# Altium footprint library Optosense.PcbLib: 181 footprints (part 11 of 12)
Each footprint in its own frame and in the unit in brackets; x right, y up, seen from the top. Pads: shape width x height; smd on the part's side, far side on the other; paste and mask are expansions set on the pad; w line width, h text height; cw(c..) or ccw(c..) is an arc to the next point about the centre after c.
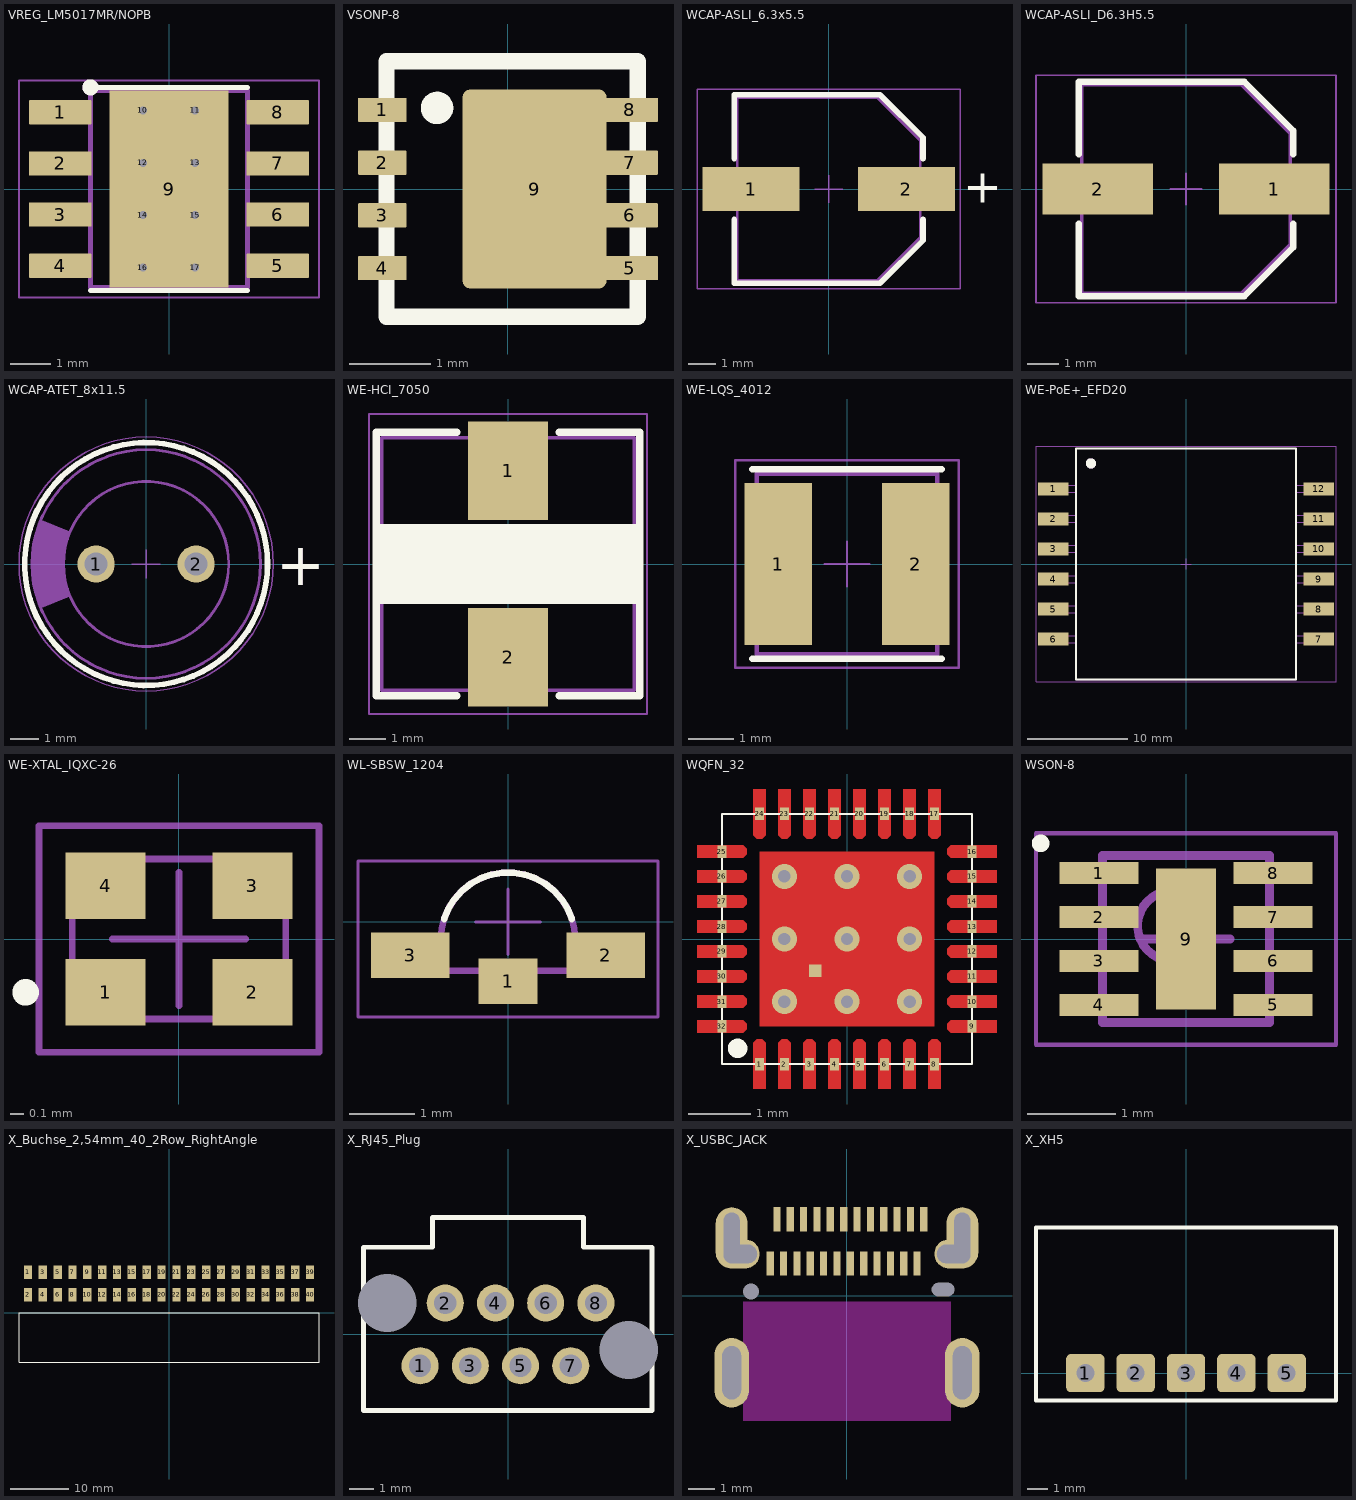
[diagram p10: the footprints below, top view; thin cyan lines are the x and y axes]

## VREG_LM5017MR/NOPB [mm]
pads (17):
  rrect5% 1.55x0.6 smd mask+0: 1(-2.7,1.905) 2(-2.7,0.635) 3(-2.7,-0.635) 4(-2.7,-1.905) 5(2.7,-1.905) 6(2.7,-0.635) 7(2.7,0.635) 8(2.7,1.905)
  rect 2.95x4.9 smd paste-3 mask+0: 9(0,0)
  round 0.3 hole 0.2: 10(-0.65,1.95) 11(0.65,1.95) 12(-0.65,0.65) 13(0.65,0.65) 14(-0.65,-0.65) 15(0.65,-0.65) 16(-0.65,-1.95) 17(0.65,-1.95)
Top Overlay:
  circle w0.2: c-1.95,2.525 r0.1
  lines w0.127: -1.95,-2.525 1.95,-2.525 ; -1.95,2.525 1.95,2.525
Top Paste:
  region: 1.355,-1.7 -1.355,-1.7 -1.355,1.7 1.355,1.7
Top Solder:
  drawing of 9 lines, arcs and shapes, not listed
Mechanical 13:
  circle w0.2: c-1.95,2.525 r0.1
  lines w0.127: -1.95,-2.45 -1.95,2.45 1.95,2.45 1.95,-2.45 -1.95,-2.45
Mechanical 15:
  lines w0.05: -3.725,-2.7 -3.725,2.7 3.725,2.7 3.725,-2.7 -3.725,-2.7
3D body "DRV8871DDA.STEP": height 1.7, standoff 0, extent -3,-2.45 3,2.45

## VSONP-8 [mm] "CSD25402Q3A"
pads (9):
  rrect10% 0.6x0.3 smd mask+0.05: 1(-1.55,0.975) 2(-1.55,0.325) 3(-1.55,-0.325) 4(-1.55,-0.975)
  rrect10% 0.7x0.3 smd mask+0.05: 5(1.5,-0.975) 6(1.5,-0.325) 7(1.5,0.325) 8(1.5,0.975)
  rrect10% 1.775x2.45 smd paste-0.55 mask+0.05: 9(0.327,0)
Top Overlay:
  circle w0.2: c-0.875,1 r0.1
  lines w0.2: -1.5,-1.575 1.6,-1.575 1.6,1.575 -1.5,1.575 -1.5,-1.575
3D body "User Library-8-VSONP3x3.step": height 0.9, standoff 0, extent -1.986,-1.9 1.784,1.9

## WCAP-ASLI_6.3x5.5 [mm] "Aluminium Electrolytic V-Chip SMT Capacitors, 6.3x5.5mm"
height 5.5
pads (2):
  rect 3.5x1.6 smd: 1(-2.8,0) 2(2.8,0)
Top Overlay:
  lines w0.2: -3.4,-1.1 -3.4,-3.4 1.85,-3.4 3.4,-1.85 3.4,-1.1 ; -3.4,1.1 -3.4,3.4 1.85,3.4 3.4,1.85 3.4,1.1
  text "+" at 4.85,-0.5 h1.22
Mechanical 13:
  lines w0.1: -3.3,-3.3 1.75,-3.3 3.3,-1.75 3.3,1.75 1.75,3.3 -3.3,3.3 -3.3,-3.3
Mechanical 15:
  lines w0.05: -0.5,0 0.5,0 ; 0,-0.5 0,0.5 ; -4.75,-3.6 -4.75,3.6 4.75,3.6 4.75,-3.6 -4.75,-3.6
3D body "6.3x5.5x2.2.stp": height 5.5, standoff 0, extent -3.65,-3.3 3.65,3.3

## WCAP-ASLI_D6.3H5.5 [mm] "Aluminium Electrolytic V-Chip SMT Capacitors, 6.3x5.5mm"
height 5.5
pads (2):
  rect 3.5x1.6 smd: 1(2.8,0) 2(-2.8,0)
Top Overlay:
  lines w0.2: -3.4,-1.1 -3.4,-3.4 1.85,-3.4 3.4,-1.85 3.4,-1.1 ; -3.4,1.1 -3.4,3.4 1.85,3.4 3.4,1.85 3.4,1.1
Mechanical 11:
  lines w0.1: -3.3,-3.3 -3.3,3.3 1.75,3.3 3.3,1.75 3.3,-1.75 1.75,-3.3 -3.3,-3.3
  text ".Designator" at -2.5,-0.75 h1.5
Mechanical 15:
  lines w0.05: -0.5,0 0.5,0 ; 0,-0.5 0,0.5 ; -4.75,-3.6 4.75,-3.6 4.75,3.6 -4.75,3.6 -4.75,-3.6
3D body "6.3x5.5x2.2.stp": height 5.5, standoff 0, extent -3.65,-3.3 3.65,3.3

## WCAP-ATET_8x11.5 [mm] "Aluminum Electrolytic Capacitors, 8x11.5mm"
height 13
pads (2):
  round 1.3 hole 0.8: 1(-1.75,0) 2(1.75,0)
Top Overlay:
  circle w0.2: c0,0 r4.25
  text "+" at 4.55,-0.75 h1.5
Mechanical 13:
  circle w0.1: c0,0 r2.89
  circle w0.1: c0,0 r4
  region: -3.685,-1.557 -3.762,-1.372 -3.881,-0.99 -3.96,-0.598 -4,-0.2 -4,0.2 -3.96,0.598 -3.881,0.99 -3.762,1.372 -3.685,1.557 -2.662,1.125 -2.662,1.124 -2.715,0.99 -2.8,0.714 -2.858,0.431 -2.886,0.144 -2.886,-0.144 -2.858,-0.431 -2.8,-0.714 -2.715,-0.99 -2.662,-1.124 -2.662,-1.125
Mechanical 15:
  circle w0.05: c0,0 r4.45
  lines w0.05: -0.5,0 0.5,0 ; 0,-0.5 0,0.5
3D body "8x11.5x3.5x0.5.stp": height 11.76, standoff -19.96, extent -3.99,-4 4,3.999

## WE-HCI_7050 [mm] "SMT Flat Wire High Current Inductor, body 6.9x6.9mm"
height 4.8
pads (2):
  rect 2.2x2.7 smd: 1(0,2.55) 2(0,-2.55)
Top Overlay:
  rectangle: -3.6,-1.092 3.6,1.092
  lines w0.2: -1.4,-3.6 -3.6,-3.6 -3.6,3.6 -1.4,3.6 ; 1.4,-3.6 3.6,-3.6 3.6,3.6 1.4,3.6
Mechanical 13:
  lines w0.1: -3.45,-3.45 -3.45,3.45 3.45,3.45 3.45,-3.45 -3.45,-3.45
Mechanical 15:
  lines w0.05: -0.5,0 0.5,0 ; 0,-0.5 0,0.5 ; -3.8,-4.1 -3.8,4.1 3.8,4.1 3.8,-4.1 -3.8,-4.1
3D body "744314xxx.stp": height 5, standoff 0, extent -3.45,-3.5 3.45,3.5

## WE-LQS_4012 [mm] "SMD Power Inductor, 2-Leads, body 4x4mm"
height 1.2
pads (2):
  rect 1.5x3.6 smd: 1(-1.525,0) 2(1.525,0)
Top Overlay:
  lines w0.15: -2.1,-2.1 2.1,-2.1 ; -2.1,2.1 2.1,2.1
Top 3D Body:
  lines w0.1: -2,-2 2,-2 2,2 -2,2 -2,-2
Top Courtyard:
  lines w0.05: -0.5,0 0.5,0 ; 0,-0.5 0,0.5 ; -2.475,-2.3 -2.475,2.3 2.475,2.3 2.475,-2.3 -2.475,-2.3
Top Component Outline:
  lines w0.1: -2,-2 2,-2 2,2 -2,2 -2,-2
Top Designator:
  text ".Designator" at -4.998,-0.333 h1
3D body "IndLQS_4012.stp": height 1.19, standoff -0.01, extent -2,-2 2,2

## WE-PoE+_EFD20 [mm] "Power over Ethernet Plus Transformer, size EFD20"
height 11.43
pads (12):
  rect 3.05x1.27 smd: 1(-13.26,7.5) 2(-13.26,4.5) 3(-13.26,1.5) 4(-13.26,-1.5) 5(-13.26,-4.5) 6(-13.26,-7.5) 7(13.26,-7.5) 8(13.26,-4.5) 9(13.26,-1.5) 10(13.26,1.5) 11(13.26,4.5) 12(13.26,7.5)
Top Overlay:
  circle w0.8: c-9.5,10.055 r0.1
  lines w0.2: -11,-11.555 -11,11.555 11,11.555 11,-11.555 -11,-11.555
Mechanical 13:
  circle w0.8: c-9.5,10.055 r0.1
  lines w0.1: -11,-7.85 -14.54,-7.85 -14.54,-7.15 -11,-7.15 ; -11,-4.85 -14.54,-4.85 -14.54,-4.15 -11,-4.15 ; -11,-1.85 -14.54,-1.85 -14.54,-1.15 -11,-1.15 ; -11,1.15 -14.54,1.15 -14.54,1.85 -11,1.85 ; -11,4.15 -14.54,4.15 -14.54,4.85 -11,4.85 ; -11,7.15 -14.54,7.15 -14.54,7.85 -11,7.85 ; 11,-7.85 14.54,-7.85 14.54,-7.15 11,-7.15 ; 11,-4.85 14.54,-4.85 14.54,-4.15 11,-4.15 ; 11,-1.85 14.54,-1.85 14.54,-1.15 11,-1.15 ; 11,1.15 14.54,1.15 14.54,1.85 11,1.85 ; 11,4.15 14.54,4.15 14.54,4.85 11,4.85 ; 11,7.15 14.54,7.15 14.54,7.85 11,7.85 ; -11,-11.555 -11,11.555 11,11.555 11,-11.555 -11,-11.555
Mechanical 15:
  lines w0.05: -0.5,0 0.5,0 ; 0,-0.5 0,0.5 ; -14.985,-11.755 -14.985,11.755 14.985,11.755 14.985,-11.755 -14.985,-11.755
3D body "EFD20_7491194501.stp": height 11.43, standoff 0, extent -14.54,-10 14.54,10

## WE-XTAL_IQXC-26 [mm] "Quartz Crystal, size IQXC-26, body 1.6x1.2mm"
height 0.4
pads (4):
  rect 0.6x0.5 smd: 1(-0.55,-0.4) 2(0.55,-0.4) 3(0.55,0.4) 4(-0.55,0.4)
Top Overlay:
  circle w0.1: c-1.15,-0.4 r0.05
Mechanical 11:
  circle w0.05: c-0.6,-0.4 r0.1
  lines w0.05: -0.8,-0.6 0.8,-0.6 0.8,0.6 -0.8,0.6 -0.8,-0.6
  text ".Designator" at -0.6,-0.25 h0.5
Mechanical 13:
  lines w0.05: -0.8,-0.6 -0.8,0.6 0.8,0.6 0.8,-0.6 -0.8,-0.6
Mechanical 15:
  lines w0.05: -0.5,0 0.5,0 ; 0,-0.5 0,0.5 ; -1.05,-0.85 -1.05,0.85 1.05,0.85 1.05,-0.85 -1.05,-0.85
3D body "FrqXTAL_IQXC-26.stp": height 0.4, standoff 0, extent -0.8,-0.6 0.8,0.6

## WL-SBSW_1204 [mm] "SMD Bi-color Side view Waterclear, body 3.2x1mm"
height 1
pads (3):
  rect 0.9x0.7 smd: 1(0,-0.91)
  rect 1.2x0.7 smd: 2(1.5,-0.51) 3(-1.5,-0.51)
Top Overlay:
  lines w0.1: -0.979,0.043 cw(c0,-0.27) 0.979,0.043
Mechanical 13:
  lines w0.1: -1.6,-0.75 1.6,-0.75 1.6,-0.27 1.028,-0.27 ccw(c0,-0.27) -1.028,-0.27 -1.6,-0.27 -1.6,-0.75
Mechanical 15:
  lines w0.05: -0.5,0 0.5,0 ; 0,-0.5 0,0.5 ; -2.3,-1.46 2.3,-1.46 2.3,0.935 -2.3,0.935 -2.3,-1.46
3D body "155124xx73200.stp": height 1.02, standoff 0.02, extent -1.6,-0.765 1.6,0.735

## WQFN_32 [mm]
pads (33):
  rect 0.15x0.2 smd paste+0 mask+0: 1(-1.4,-2) 2(-1,-2) 3(-0.6,-2) 4(-0.2,-2) 5(0.2,-2) 6(0.6,-2) 7(1,-2) 8(1.4,-2) 9(2,-1.4) 10(2,-1) 11(2,-0.6) 12(2,-0.2) 13(2,0.2) 14(2,0.6) 15(2,1) 16(2,1.4) 17(1.4,2) 18(1,2) 19(0.6,2) 20(0.2,2) 21(-0.2,2) 22(-0.6,2) 23(-1,2) 24(-1.4,2) 25(-2,1.4) 26(-2,1) 27(-2,0.6) 28(-2,0.2) 29(-2,-0.2) 30(-2,-0.6) 31(-2,-1) 32(-2,-1.4)
  rect 0.2x0.2 smd paste+0 mask+0: Pad(-0.508,-0.508)
via 1,0 diameter 0.4 hole 0.2
via 0,0 diameter 0.4 hole 0.2
via -1,0 diameter 0.4 hole 0.2
via -1,-1 diameter 0.4 hole 0.2
via 1,-1 diameter 0.4 hole 0.2
via 0,-1 diameter 0.4 hole 0.2
via -1,1 diameter 0.4 hole 0.2
via 1,1 diameter 0.4 hole 0.2
via 0,1 diameter 0.4 hole 0.2
Top Layer:
  rectangle: -1.4,-1.4 1.4,1.4
  region: -2.4,1.5 -2.4,1.3 -1.7,1.3 -1.659,1.3 -1.6,1.359 -1.6,1.441 -1.659,1.5 -1.7,1.5
  region: -2.4,1.1 -2.4,0.9 -1.7,0.9 -1.659,0.9 -1.6,0.959 -1.6,1.041 -1.659,1.1 -1.7,1.1
  region: -2.4,0.7 -2.4,0.5 -1.7,0.5 -1.659,0.5 -1.6,0.559 -1.6,0.641 -1.659,0.7 -1.7,0.7
  region: -2.4,0.3 -2.4,0.1 -1.7,0.1 -1.659,0.1 -1.6,0.159 -1.6,0.241 -1.659,0.3 -1.7,0.3
  region: -2.4,-0.1 -2.4,-0.3 -1.7,-0.3 -1.659,-0.3 -1.6,-0.241 -1.6,-0.159 -1.659,-0.1 -1.7,-0.1
  region: -2.4,-0.5 -2.4,-0.7 -1.7,-0.7 -1.659,-0.7 -1.6,-0.641 -1.6,-0.559 -1.659,-0.5 -1.7,-0.5
  region: -2.4,-0.9 -2.4,-1.1 -1.7,-1.1 -1.659,-1.1 -1.6,-1.041 -1.6,-0.959 -1.659,-0.9 -1.7,-0.9
  region: -1.3,2.4 -1.5,2.4 -1.5,1.7 -1.5,1.659 -1.441,1.6 -1.359,1.6 -1.3,1.659 -1.3,1.7
  region: -0.9,2.4 -1.1,2.4 -1.1,1.7 -1.1,1.659 -1.041,1.6 -0.959,1.6 -0.9,1.659 -0.9,1.7
  region: -0.5,2.4 -0.7,2.4 -0.7,1.7 -0.7,1.659 -0.641,1.6 -0.559,1.6 -0.5,1.659 -0.5,1.7
  region: -0.1,2.4 -0.3,2.4 -0.3,1.7 -0.3,1.659 -0.241,1.6 -0.159,1.6 -0.1,1.659 -0.1,1.7
  region: 0.3,2.4 0.1,2.4 0.1,1.7 0.1,1.659 0.159,1.6 0.241,1.6 0.3,1.659 0.3,1.7
  region: 0.7,2.4 0.5,2.4 0.5,1.7 0.5,1.659 0.559,1.6 0.641,1.6 0.7,1.659 0.7,1.7
  region: 1.1,2.4 0.9,2.4 0.9,1.7 0.9,1.659 0.959,1.6 1.041,1.6 1.1,1.659 1.1,1.7
  region: 2.4,-1.5 2.4,-1.3 1.7,-1.3 1.659,-1.3 1.6,-1.359 1.6,-1.441 1.659,-1.5 1.7,-1.5
  region: 2.4,1.3 2.4,1.5 1.7,1.5 1.659,1.5 1.6,1.441 1.6,1.359 1.659,1.3 1.7,1.3
  region: 2.4,0.9 2.4,1.1 1.7,1.1 1.659,1.1 1.6,1.041 1.6,0.959 1.659,0.9 1.7,0.9
  region: 2.4,0.5 2.4,0.7 1.7,0.7 1.659,0.7 1.6,0.641 1.6,0.559 1.659,0.5 1.7,0.5
  region: 2.4,0.1 2.4,0.3 1.7,0.3 1.659,0.3 1.6,0.241 1.6,0.159 1.659,0.1 1.7,0.1
  region: 2.4,-0.3 2.4,-0.1 1.7,-0.1 1.659,-0.1 1.6,-0.159 1.6,-0.241 1.659,-0.3 1.7,-0.3
  region: 2.4,-0.7 2.4,-0.5 1.7,-0.5 1.659,-0.5 1.6,-0.559 1.6,-0.641 1.659,-0.7 1.7,-0.7
  region: 2.4,-1.1 2.4,-0.9 1.7,-0.9 1.659,-0.9 1.6,-0.959 1.6,-1.041 1.659,-1.1 1.7,-1.1
  region: -2.4,-1.3 -2.4,-1.5 -1.7,-1.5 -1.659,-1.5 -1.6,-1.441 -1.6,-1.359 -1.659,-1.3 -1.7,-1.3
  region: 0.9,-2.4 1.1,-2.4 1.1,-1.7 1.1,-1.659 1.041,-1.6 0.959,-1.6 0.9,-1.659 0.9,-1.7
  region: 0.5,-2.4 0.7,-2.4 0.7,-1.7 0.7,-1.659 0.641,-1.6 0.559,-1.6 0.5,-1.659 0.5,-1.7
  region: 0.1,-2.4 0.3,-2.4 0.3,-1.7 0.3,-1.659 0.241,-1.6 0.159,-1.6 0.1,-1.659 0.1,-1.7
  region: -0.3,-2.4 -0.1,-2.4 -0.1,-1.7 -0.1,-1.659 -0.159,-1.6 -0.241,-1.6 -0.3,-1.659 -0.3,-1.7
  region: -0.7,-2.4 -0.5,-2.4 -0.5,-1.7 -0.5,-1.659 -0.559,-1.6 -0.641,-1.6 -0.7,-1.659 -0.7,-1.7
  region: -1.1,-2.4 -0.9,-2.4 -0.9,-1.7 -0.9,-1.659 -0.959,-1.6 -1.041,-1.6 -1.1,-1.659 -1.1,-1.7
  region: -1.5,-2.4 -1.3,-2.4 -1.3,-1.7 -1.3,-1.659 -1.359,-1.6 -1.441,-1.6 -1.5,-1.659 -1.5,-1.7
  region: 1.3,-2.4 1.5,-2.4 1.5,-1.7 1.5,-1.659 1.441,-1.6 1.359,-1.6 1.3,-1.659 1.3,-1.7
  region: 1.5,2.4 1.3,2.4 1.3,1.7 1.3,1.659 1.359,1.6 1.441,1.6 1.5,1.659 1.5,1.7
Top Overlay:
  circle w0.2: c-1.75,-1.75 r0.056
  lines w0.025: -2,-2 -2,2 2,2 2,-2 -2,-2
Top Paste:
  rectangle: -1.35,0.15 -0.15,1.35
  rectangle: 0.15,-1.35 1.35,-0.15
  rectangle: -1.35,-1.35 -0.15,-0.15
  rectangle: 0.15,0.15 1.35,1.35
3D body "RSN0032B.stp": height 0.8, standoff 0, extent -2,-2 2,2

## WSON-8 [mm] "SON, 8-Leads, Body 2,00x2,00mm, Pitch 0,50mm, Thermal Pad 1,60x0,68mm, IPC Medium Density"
height 0.8
pads (9):
  rect 0.9x0.25 smd: 1(-0.99,0.75) 2(-0.99,0.25) 3(-0.99,-0.25) 4(-0.99,-0.75) 5(0.99,-0.75) 6(0.99,-0.25) 7(0.99,0.25) 8(0.99,0.75)
  rect 0.68x1.6 smd: 9(0,0)
Top Overlay:
  circle w0.1: c-1.652,1.087 r0.05
Top Courtyard:
  lines w0.05: -1.705,-1.2 1.705,-1.2 1.705,1.2 -1.705,1.2 -1.705,-1.2
  lines w0.1: -0.5,0 0.5,0 ; 0,-0.5 0,0.5
Top Assembly:
  circle w0.1: c-0.15,0.15 r0.4
  lines w0.1: -0.95,-0.95 0.95,-0.95 0.95,0.95 -0.95,0.95 -0.95,-0.95
3D body: height 0.8, standoff 0.1, extent -0.95,-0.95 0.95,0.95

## X_Buchse_2,54mm_40_2Row_RightAngle [mm]
pads (40):
  rect 1.42x2.24 smd: 1(-24.13,6.88) 3(-21.59,6.88) 5(-19.05,6.88) 7(-16.51,6.88) 9(-13.97,6.88) 11(-11.43,6.88) 13(-8.89,6.88) 15(-6.35,6.88) 17(-3.81,6.88) 19(-1.27,6.88) 21(1.27,6.88) 23(3.81,6.88) 25(6.35,6.88) 27(8.89,6.88) 29(11.43,6.88) 31(13.97,6.88) 33(16.51,6.88) 35(19.05,6.88) 37(21.59,6.88) 39(24.13,6.88)
  rect 1.42x2.34 smd: 2(-24.13,3.02) 4(-21.59,3.02) 6(-19.05,3.02) 8(-16.51,3.02) 10(-13.97,3.02) 12(-11.43,3.02) 14(-8.89,3.02) 16(-6.35,3.02) 18(-3.81,3.02) 20(-1.27,3.02) 22(1.27,3.02) 24(3.81,3.02) 26(6.35,3.02) 28(8.89,3.02) 30(11.43,3.02) 32(13.97,3.02) 34(16.51,3.02) 36(19.05,3.02) 38(21.59,3.02) 40(24.13,3.02)
Top Overlay:
  lines w0.2: -25.654,-8.509 25.654,-8.509 25.654,0 -25.654,0 -25.654,-8.509

## X_RJ45_Plug [mm]
height 11
pads (10):
  round 1.5 hole 0.9: 1(-3.556,-1.27) 2(-2.54,1.27) 3(-1.524,-1.27) 4(-0.508,1.27) 5(0.508,-1.27) 6(1.524,1.27) 7(2.54,-1.27) 8(3.556,1.27)
  round 1.5 hole 2.36: ""(-4.89,1.27) ""(4.89,-0.635)
Top Overlay:
  lines w0.2: -5.85,-3.075 5.825,-3.075 5.825,3.525 3.05,3.525 3.05,4.725 -3.05,4.725 -3.05,3.525 -5.85,3.525 -5.85,-3.075

## X_USBC_JACK [mm] "10137065-00021LF"
pads (33):
  rect 0.27x0.9 smd: A01(-2.625,2.875) A02(-2.125,2.875) A03(-1.625,2.875) A04(-1.125,2.875) A05(-0.625,2.875) A06(-0.125,2.875) A07(0.375,2.875) A08(0.875,2.875) A09(1.375,2.875) A10(1.875,2.875) A11(2.375,2.875) A12(2.875,2.875) B01(2.625,1.225) B02(2.125,1.225) B03(1.625,1.225) B04(1.125,1.225) B05(0.625,1.225) B06(0.125,1.225) B07(-0.375,1.225) B08(-0.875,1.225) B09(-1.375,1.225) B10(-1.875,1.225) B11(-2.375,1.225) B12(-2.875,1.225) B12(-2.875,1.225)
  oval 1.3x2.6 hole 0.7 slot 2 at 90 deg: ""(-4.32,-2.875) ""(4.32,-2.875)
  oval 1.2x2.3 hole 0.6 slot 1.9 at 90 deg: ""(-4.32,2.175) ""(4.32,2.175)
  oval 1.45x1.1 hole 0.7 slot 1.25 at 0 deg: ""(-3.995,1.575) ""(3.995,1.575)
  round 0 hole 0.6 unplated: ""(-3.6,0.175)
  round 0 hole 0.5 slot 0.85 at 0 deg unplated: ""(3.6,0.24)
Keep-Out Layer:
  rectangle: -3.9,-4.675 3.9,-0.2
3D body "10137065..stp": height 3.17, standoff -0.6, extent -4.49,-5.1 4.45,3.05

## X_XH5 [mm]
pads (5):
  rrect25% 1.9x1.9 hole 0.9: 1(-5,0) 2(-2.5,0) 3(0,0) 4(2.5,0) 5(5,0)
Top Overlay:
  lines w0.2: -7.45,7.225 -7.45,-1.359 7.45,-1.359 7.45,7.196 ; -7.45,7.23 7.45,7.23
3D body "User Library-JST-XH-2_5mm-5.step": height 5.95, standoff -3.35, extent -7.522,-0.398 7.478,7.242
